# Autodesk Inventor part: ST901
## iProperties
Created: 2007-01
Part Number: ST901
Material: -
Description: Vis CHc, ISO 4762 - M6 x 12
Document SubType Name: Modeling
Standard: ISO 4762
Designer: Gilles GLEMAREC
Standard Revision: Quatrième édition 2004-03-01
Standards Organization: ISO
Language: fr-FR
Size Designation: M6 x 12
Categories: <MemberInstance Version="R10.0.0"><Categories><Category DisplayName="Visserie" InternalName="e4da775c-781d-43d5-af7c-5136215cf5a6" Mnemonic="FSTN"><Category Dis
Stock Number: ST901
Author: Gilles GLEMAREC
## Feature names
1. Corps [Revolution]
2. Rainure [Extrusion]
3. Congé1 [Fillet]
4. Chanfrein1 [Chamfer]
